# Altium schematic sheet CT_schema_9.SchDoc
size 277 x 170 mm
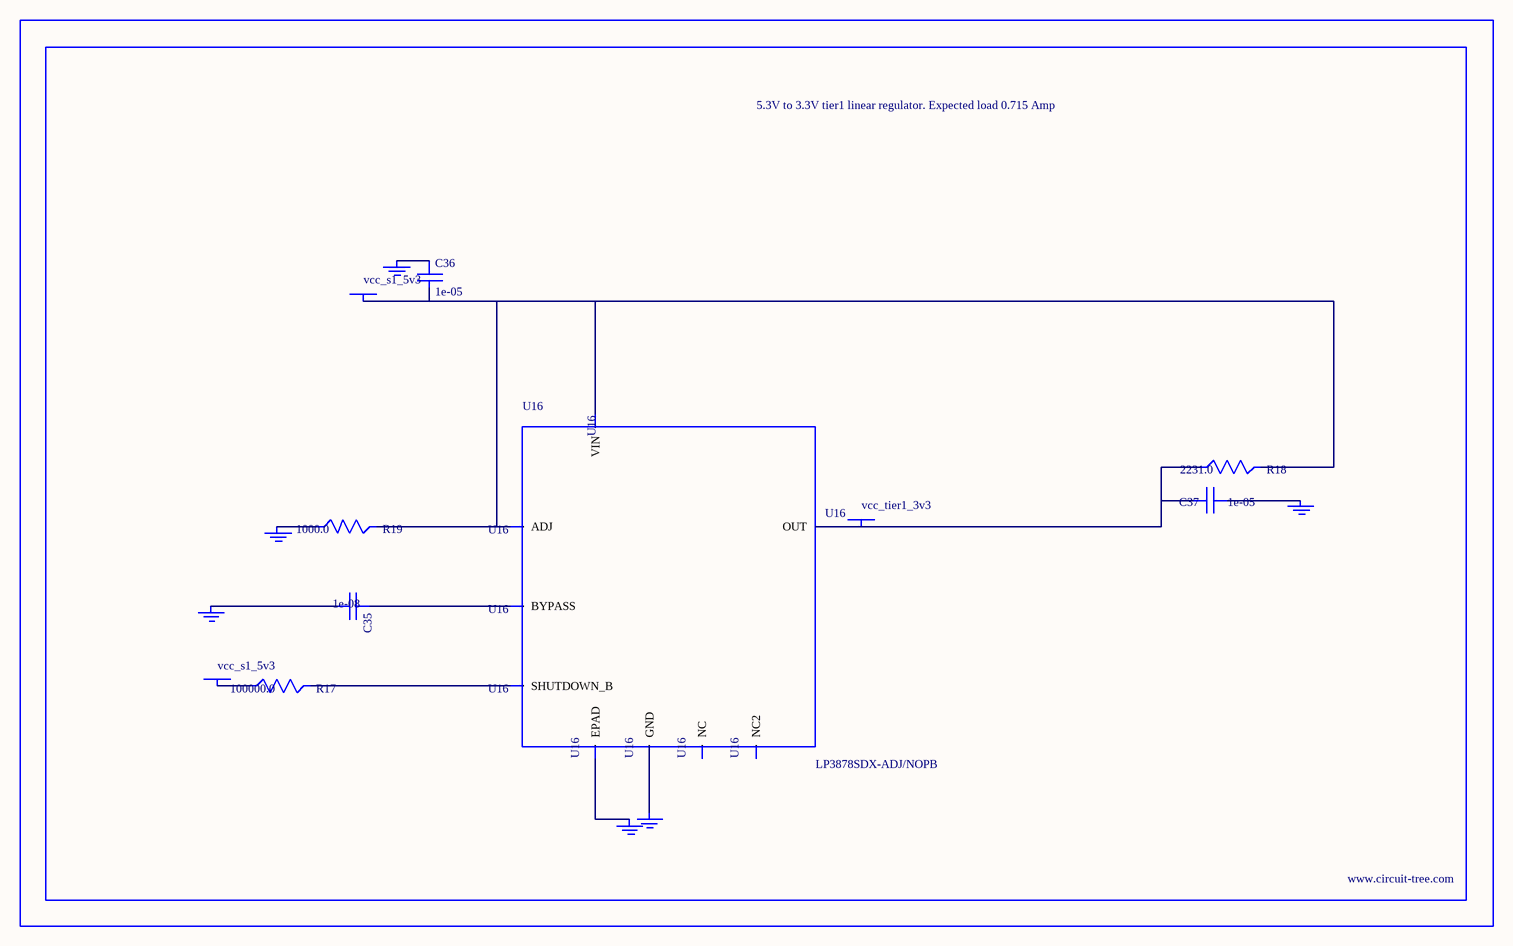
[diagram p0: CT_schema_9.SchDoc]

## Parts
BORDER8  (no value)
C35  1e-08  [C0402]
C36  1e-05  [C1206]
C37  1e-05  [C1210]
GND_INSTANCE_8_0  (no value)
GND_INSTANCE_8_1  (no value)
GND_INSTANCE_8_2  (no value)
GND_INSTANCE_8_3  (no value)
GND_INSTANCE_8_4  (no value)
GND_INSTANCE_8_5  (no value)
POWER_INSTANCE_8_0  vcc_s1_5v3
POWER_INSTANCE_8_1  vcc_s1_5v3
POWER_INSTANCE_8_2  vcc_tier1_3v3
R17  100000.0  [R0603]
R18  2231.0  [R0603]
R19  1000.0  [R0603]
U16  LP3878SDX-ADJ/NOPB  [WSON-8]

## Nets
NetC35_1: C35.1 U16.1(BYPASS)
NetC35_2: C35.2 GND_INSTANCE_8_0.0(GND)
NetC36_1: C36.1 GND_INSTANCE_8_1.0(GND)
NetC36_2: C36.2 POWER_INSTANCE_8_0.0(PWR) R18.2 R19.2 U16.4(VIN) U16.6(ADJ)
NetC37_1: C37.1 GND_INSTANCE_8_2.0(GND)
NetC37_2: C37.2 POWER_INSTANCE_8_2.0(PWR) R18.1 U16.5(OUT)
NetGND_INSTANCE_8_3_0: GND_INSTANCE_8_3.0(GND) R19.1
NetGND_INSTANCE_8_4_0: GND_INSTANCE_8_4.0(GND) U16.PAD(EPAD)
NetGND_INSTANCE_8_5_0: GND_INSTANCE_8_5.0(GND) U16.3(GND)
NetPOWER_INSTANCE_8_1_0: POWER_INSTANCE_8_1.0(PWR) R17.1
NetR17_2: R17.2 U16.8(SHUTDOWN_B)

Not connected (* = marked no-connect by the designer): U16 2(NC) 7(NC2)

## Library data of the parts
BORDER8 = BORDER_PAGE8
C35 = C0402C103K3RAC
C36 = C1206C106K3RACTU
C37 = GRM32DR61E106MA12L
GND_INSTANCE_8_0-GND_INSTANCE_8_5 = GND
POWER_INSTANCE_8_0-POWER_INSTANCE_8_2 = PWR
R17 = RC0603JR-07100KL
R18 = R18
R19 = RC0603JR-071KL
